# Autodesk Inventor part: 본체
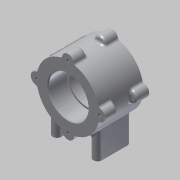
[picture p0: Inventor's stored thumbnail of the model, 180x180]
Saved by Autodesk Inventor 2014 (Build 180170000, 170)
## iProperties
Created: 2015-03
Part Number: 본체
Material: 알루미늄 6061
Document SubType Name: Modeling
Designer: MYHOME
Mass: 450.761 g
Surface Area: 333.126 cm^2
Volume: 166.332 cm^3
Density: 2.71 g/cm^3
Appearance: 알루미늄 - 평지
Author: MYHOME
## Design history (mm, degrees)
sketch "스케치2"
  geometry: C1 r 37 at (0, 56); 1 further point
  constraints: 1 centre point, 1 vertical alignment
  dimensions: "d0" = 74 diameter of C1; "d1" = 56 distance of point (0, 0) C1.centre
extrude "돌출1" new body sketch "스케치2" stored distance "d2" = 52; taper "d3" = 0 deg
sketch "스케치3"
  geometry: C1 r 7 at (0, 37); C2 r 7 at (37, 0); C3 r 7 at (0, -37); C4 r 7 at (-37, 0); A1 r 37 centre (0, 0) between (0, 37) and (37, 0) reference; 1 further point
  constraints: 4 centre point, 4 point on circle, 2 horizontal alignment, 2 vertical alignment
  dimensions: "d4" = 7 radius of C1; "d5" = 7 radius of C2; "d6" = 7 radius of C3; "d7" = 7 radius of C4
extrude "돌출2" join sketch "스케치3" distance "d8" = 15; taper "d9" = 0 deg
hole "구멍1" diameter "d12" = 42; stored, may be unused: countersink angle "d16" = 90 deg, drill point angle "d18" = 0 deg; dims "d10" = 10, "d11" = 10, "d13" = 6, "d14" = 47, "d15" = 22, "d17" = 8
sketch "스케치4"
  geometry: A1 r 7 centre (0, 19) between (-6.969, 19.662) and (6.969, 19.662) reference; A2 r 7 centre (37, 56) between (36.338, 49.031) and (36.338, 62.969) reference; A3 r 7 centre (0, 93) between (6.969, 92.338) and (-6.969, 92.338) reference; A4 r 7 centre (-37, 56) between (-36.338, 62.969) and (-36.338, 49.031) reference; 5 further points
  constraints: 4 coincident
hole "구멍2" sketch "스케치4" at (-37, 56), (0, 93), (37, 56), (0, 19) diameter "d19" = 3.242; stored, may be unused: countersink angle "d23" = 90 deg, drill point angle "d25" = 118 deg; dims "d20" = 8, "d21" = 47, "d22" = 22, "d24" = 11
chamfer "모따기1" distance "d26" = 1; stored, may be unused: second distance "d27" = 2, angle "d28" = 45 deg
sketch "스케치5"
  geometry: C1 r 21 at (0, -56) reference; C2 r 23.5 at (0, -56); 1 further point
  constraints: 1 centre point, 1 coincident
  dimensions: "d29" = 47 diameter of C2
extrude "돌출3" cut sketch "스케치5" distance "d30" = 22; taper "d31" = 0 deg
chamfer "모따기2" distance "d32" = 1; stored, may be unused: second distance "d33" = 2, angle "d34" = 45 deg
sketch "스케치6"
  geometry: L1 (-24, 15)-(-24, -15); L2 (-29, 15)-(-29, -15); L3 (-19, -15)-(-19, 15); L4 (24, 15)-(24, -15); L5 (19, 15)-(19, -15); L6 (29, -15)-(29, 15); A1 r 5 centre (-24, 15) between (-19, 15) and (-29, 15); A2 r 5 centre (-24, -15) between (-29, -15) and (-19, -15); A3 r 5 centre (24, 15) between (29, 15) and (19, 15); A4 r 5 centre (24, -15) between (19, -15) and (29, -15); 3 further points
  constraints: 16 end point, 8 point on circle, 8 tangent, 4 centre point, 4 parallel, 2 horizontal alignment, 2 midpoint, 1 equal radius, 1 vertical
  dimensions: "d35" = 40 dimension on A3 A4; "d36" = 5 radius of A3; "d37" = 48 distance of L1.end L4.end; "d38" = 24 distance of point (24, 0) point (0, 0)
extrude "돌출4" join sketch "스케치6" stored distance "d39" = 22; taper "d40" = 0 deg
sketch "스케치7"
  geometry: L1 (-19, 15)-(-19, -15) reference; L2 (-29, -15)-(-29, 15) reference; A1 r 5 centre (24, 15) between (29, 15) and (19, 15) reference; A2 r 5 centre (24, -15) between (19, -15) and (29, -15) reference; A3 r 5 centre (-24, 15) between (-19, 15) and (-29, 15) reference; A4 r 5 centre (-24, -15) between (-29, -15) and (-19, -15) reference; 5 further points
  constraints: 4 coincident
hole "구멍3" sketch "스케치7" at (-24, 15), (-24, -15), (24, -15), (24, 15) diameter "d41" = 4.134; stored, may be unused: countersink angle "d45" = 90 deg, drill point angle "d47" = 118 deg; dims "d42" = 6, "d43" = 47, "d44" = 22, "d46" = 8
fillet "모깎기1" dims "d48" = 3
fillet "모깎기2" dims "d49" = 3
fillet "모깎기3" dims "d50" = 3
sketch "스케치8"
  geometry: L1 (0, 56)-(0, 93); L2 (0, 56)-(26.163, 82.163); C1 r 1.621 at (0, 19) reference; C2 r 1.621 at (0, 93) reference; C3 r 1.621 at (37, 56) reference; C4 r 1.621 at (-37, 56) reference; C5 r 24.5 at (0, 56) reference; A1 r 37 centre (0, 56) between (35.863, 65.104) and (9.104, 91.863) reference; A2 r 3 centre (9.842, 94.77) between (6.889, 94.239) and (9.104, 91.863) reference; A3 r 7 centre (0, 93) between (6.889, 94.239) and (-6.889, 94.239) reference; A4 r 3 centre (-9.842, 94.77) between (-9.104, 91.863) and (-6.889, 94.239) reference; A5 r 37 centre (0, 56) between (-9.104, 91.863) and (-35.863, 65.104) reference; A6 r 3 centre (-38.77, 65.842) between (-38.239, 62.889) and (-35.863, 65.104) reference; A7 r 7 centre (-37, 56) between (-38.239, 62.889) and (-38.239, 49.111) reference; A8 r 3 centre (-38.77, 46.158) between (-35.863, 46.896) and (-38.239, 49.111) reference; A9 r 37 centre (0, 56) between (-35.863, 46.896) and (-9.104, 20.138) reference; A10 r 3 centre (-9.842, 17.23) between (-6.889, 17.761) and (-9.104, 20.138) reference; A11 r 7 centre (0, 19) between (-6.889, 17.761) and (6.889, 17.761) reference; A12 r 3 centre (9.842, 17.23) between (9.104, 20.138) and (6.889, 17.761) reference; A13 r 37 centre (0, 56) between (9.104, 20.138) and (35.863, 46.896) reference; A14 r 3 centre (38.77, 46.158) between (38.239, 49.111) and (35.863, 46.896) reference; A15 r 7 centre (37, 56) between (38.239, 49.111) and (38.239, 62.889) reference; A16 r 3 centre (38.77, 65.842) between (35.863, 65.104) and (38.239, 62.889) reference; 2 further points
  constraints: 4 end point, 1 coincident, 1 point on circle, 1 vertical
  dimensions: "d51" = 45 deg angle of L1 L2
  node "투영된 루프2"
node "작업 평면2"
  node "작업 평면1"
sketch "스케치9"
  geometry: L1 (-26, 18.921)-(-26, -18.921) reference; 4 further points
  constraints: 2 coincident, 1 other
  dimensions: "d55" = 26 distance from line of L1 point (0, 0)
feature "엠보싱1" sketch "스케치9" dims "d53" = 0.5, "d54" = 0
fillet "모깎기4" dims "d56" = 0.3
node "솔리드1"
mirror "대칭1"
node "투영된 루프1"
other parameters: "d52" = 0.5
